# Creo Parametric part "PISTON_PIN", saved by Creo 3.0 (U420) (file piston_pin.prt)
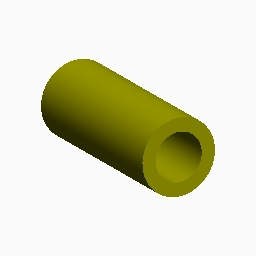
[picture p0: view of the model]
Units: millimeter Kilogram Sec (mmKs); MM, KILOGRAM, SECS

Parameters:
  MATERIAL = "ZLl09G"

Created from: PISTON.PRT

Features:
  1. datum plane "RIGHT"
  2. datum plane "TOP"
  3. datum plane "FRONT"
  4. coordinate system
  5. protrusion

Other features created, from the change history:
  extrusion "Extrude 8"
  mirror "Mirror 3"
  extrusion "Extrude 8 (2)"
  round "Round 10" (2 times)
  round "Round 11" (2 times)
  round "Round 12"
  round "Round 13"
  revolved cut "Revolve 1"
  chamfer "Chamfer 1"
  extruded cut "Extrude 9"
  round "Round 14"
  extrusion "Extrude 10" (2 times)
  round "Round 15"
  round "Round 16"
  round "Round 17"
  round "Round 18"
  datum plane "DTM2"
  datum axis "A_14"
  extrusion "Extrude 9"
  mirror "Mirror 4"
  round "Round 7"
  round "Round 8"
  mirror "Mirror 5"
  round "Round 9"
  mirror "Mirror 6"

Surfaces: 5 plane, 4 cylinder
